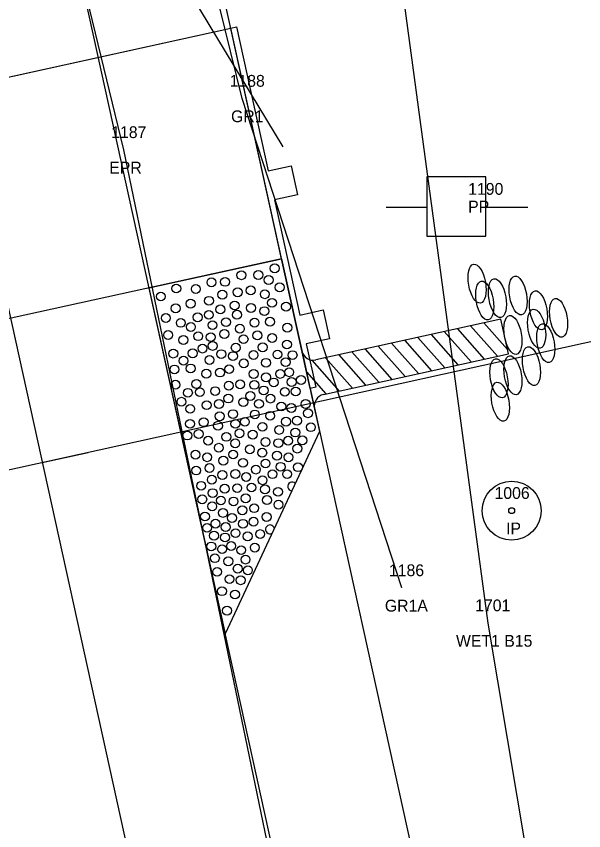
# Model space of a CAD drawing. Extents: x 2522090 to 2524658, y 882711 to 887512.
# Drawn here: x 2523808.5 to 2523856.5, y 884993.3 to 885062.2 of the extents above; entities that cross this region are included whole.
import ezdxf

# ---------------------------------------------------------------- set-up
doc = ezdxf.new("R2010")
doc.units = 0
for name, color, linetype in [('RD_EV_JurisArea', 7, 'Continuous'), ('RD_EX_DV_Prop_txCode', 7, 'Continuous'), ('RD_EX_DV_PropPin', 7, 'Continuous'), ('RD_EX_GuardRail', 7, 'Continuous'), ('RD_EX_GuardRail_txCode', 7, 'Continuous'), ('RD_EX_H2O_WetLd_txCode', 7, 'Continuous'), ('RD_EX_Road', 7, 'Continuous'), ('RD_EX_Road_txCode', 7, 'Continuous'), ('RD_EX_UT', 7, 'Continuous'), ('RD_EX_UT_txCode', 7, 'Continuous'), ('RD_HC_Cl', 7, 'Continuous'), ('RD_HC_Data_Tic', 7, 'Continuous'), ('RD_PD_Bridge', 7, 'Continuous'), ('RD_PD_Final_TrvlWay', 7, 'Continuous'), ('RD_PD_GR', 7, 'Continuous'), ('RD_PD_PatLn5', 7, 'Continuous'), ('RD_PD_PatLn6', 7, 'Continuous'), ('RD_PD_PaveShd', 7, 'Continuous'), ('RD_SMD_Locator', 7, 'Continuous')]:
    doc.layers.add(name, color=color, linetype=linetype)

# ---------------------------------------------------------------- blocks, each defined once
blk = doc.blocks.new('TBC1')
at = {"layer": 'RD_PD_GR'}
blk.add_lwpolyline([(12.5, 2.5), (15, 2.5), (15, 0.492), (25, 0.492), (25, 2.5), (27.5, 2.5), (27.5, 0.492), (31.25, 0.492), (31.25, 0), (0, 0), (0, 0.492), (12.5, 0.492)], close=True, dxfattribs=at)

msp = doc.modelspace()

# ---------------------------------------------------------------- linework, layer by layer
at = {"layer": 'RD_EV_JurisArea'}
msp.add_lwpolyline([(2523944.864, 884550.08), (2523910.413, 884709.577), (2523888.007, 884815.03), (2523863.93, 884918.366), (2523848.427, 885010.841), (2523837.066, 885095.132), (2523817.825, 885104.474)], dxfattribs=at)
at = {"layer": 'RD_EX_DV_PropPin'}
for centre, radius in [((2523850.412, 885020.357), 2.499), ((2523850.412, 885020.358), 0.25)]:
    msp.add_circle(centre, radius, dxfattribs=at)
at = {"layer": 'RD_EX_GuardRail'}
msp.add_lwpolyline([(2523841.112, 885013.814), (2523827.604, 885055.265), (2523819.275, 885089.086)], dxfattribs=at)
at = {"layer": 'RD_EX_Road'}
for p, q in [((2523817.578, 885050.917), (2523809.375, 885084.881)), ((2523837.97, 884952.456), (2523817.578, 885050.917))]:
    msp.add_line(p, q, dxfattribs=at)
at = {"layer": 'RD_EX_UT'}
for p, q in [((2523848.225, 885048.623), (2523843.225, 885048.623)), ((2523843.225, 885048.623), (2523843.225, 885043.623)), ((2523848.225, 885043.623), (2523848.225, 885048.623)), ((2523839.793, 885046.061), (2523843.263, 885046.061)), ((2523848.153, 885046.061), (2523851.793, 885046.061)), ((2523843.225, 885043.623), (2523848.225, 885043.623))]:
    msp.add_line(p, q, dxfattribs=at)
at = {"layer": 'RD_HC_Cl'}
msp.add_line((2523641.165, 885794.201), (2524197.759, 883266.557), dxfattribs=at)
at = {"layer": 'RD_HC_Data_Tic'}
msp.add_line((2523810.669, 885024.44), (2523814.575, 885025.3), dxfattribs=at)
at = {"layer": 'RD_PD_Bridge'}
for p, q in [((2523780.729, 885051.128), (2523826.629, 885061.235)), ((2523830.93, 885041.703), (2523785.03, 885031.596))]:
    msp.add_line(p, q, dxfattribs=at)
for points in [[(2523830.93, 885041.703), (2523794.372, 885207.726)], [(2523780.729, 885051.128), (2523826.629, 885061.235)]]:
    msp.add_lwpolyline(points, dxfattribs=at)
at = {"layer": 'RD_PD_Final_TrvlWay'}
msp.add_line((2523722.39, 885481.141), (2524037.438, 884050.417), dxfattribs=at)
at = {"layer": 'RD_PD_GR'}
msp.add_line((2523833.35, 885030.716), (2523900.015, 884727.969), dxfattribs=at)
at = {"layer": 'RD_PD_PatLn5'}
msp.add_line((2523888.797, 885041.644), (2523732.541, 885007.236), dxfattribs=at)
at = {"layer": 'RD_PD_PatLn6'}
msp.add_line((2523748.348, 885188.144), (2523831.037, 885051.167), dxfattribs=at)
at = {"layer": 'RD_PD_PaveShd'}
for p, q in [((2523819.699, 885039.23), (2523830.93, 885041.703)), ((2523832.866, 885032.914), (2523830.93, 885041.703)), ((2523830.93, 885041.703), (2523832.866, 885032.914)), ((2523819.699, 885039.23), (2523826.151, 885009.932)), ((2523849.487, 885036.583), (2523833.843, 885033.129)), ((2523850.134, 885033.653), (2523849.487, 885036.583)), ((2523850.134, 885033.653), (2523849.487, 885036.583)), ((2523845.826, 885035.775), (2523848.1, 885033.204)), ((2523845.826, 885035.775), (2523848.1, 885033.204)), ((2523846.943, 885036.021), (2523849.217, 885033.451)), ((2523846.943, 885036.021), (2523849.217, 885033.451)), ((2523848.06, 885036.268), (2523850.054, 885034.014)), ((2523848.06, 885036.268), (2523850.054, 885034.014)), ((2523842.475, 885035.035), (2523844.749, 885032.465)), ((2523842.475, 885035.035), (2523844.749, 885032.465)), ((2523843.592, 885035.282), (2523845.866, 885032.711)), ((2523843.592, 885035.282), (2523845.866, 885032.711)), ((2523844.709, 885035.528), (2523846.983, 885032.958)), ((2523844.709, 885035.528), (2523846.983, 885032.958)), ((2523839.124, 885034.295), (2523841.398, 885031.725)), ((2523839.124, 885034.295), (2523841.398, 885031.725)), ((2523840.241, 885034.542), (2523842.515, 885031.972)), ((2523840.241, 885034.542), (2523842.515, 885031.972)), ((2523841.358, 885034.788), (2523843.632, 885032.218)), ((2523841.358, 885034.788), (2523843.632, 885032.218)), ((2523834.487, 885030.199), (2523850.134, 885033.653)), ((2523835.773, 885033.556), (2523838.047, 885030.985)), ((2523835.773, 885033.556), (2523838.047, 885030.985)), ((2523836.89, 885033.802), (2523839.164, 885031.232)), ((2523836.89, 885033.802), (2523839.164, 885031.232)), ((2523838.007, 885034.049), (2523840.281, 885031.478)), ((2523838.007, 885034.049), (2523840.281, 885031.478)), ((2523832.866, 885032.914), (2523833.511, 885029.984)), ((2523833.492, 885033.115), (2523835.813, 885030.492)), ((2523834.656, 885033.309), (2523836.93, 885030.739)), ((2523834.656, 885033.309), (2523836.93, 885030.739)), ((2523833.042, 885032.115), (2523834.696, 885030.246)), ((2523833.08, 885031.943), (2523833.08, 885031.943)), ((2523833.511, 885029.984), (2523834.156, 885027.054)), ((2523834.156, 885027.054), (2523826.151, 885009.932))]:
    msp.add_line(p, q, dxfattribs=at)
for centre in [(2523830.349, 885040.885), (2523830.349, 885040.885), (2523827.534, 885040.3), (2523827.534, 885040.3), (2523828.967, 885040.325), (2523828.967, 885040.325), (2523828.967, 885040.325), (2523824.999, 885039.698), (2523824.999, 885039.698), (2523826.153, 885039.739), (2523826.153, 885039.739), (2523829.845, 885039.899), (2523822.02, 885039.178), (2523822.02, 885039.178), (2523823.673, 885039.133), (2523823.673, 885039.133), (2523827.222, 885038.86), (2523827.222, 885038.86), (2523828.326, 885039.017), (2523828.326, 885039.017), (2523829.513, 885038.692), (2523829.513, 885038.692), (2523830.772, 885039.275), (2523830.772, 885039.275), (2523820.715, 885038.501), (2523820.715, 885038.501), (2523824.791, 885038.139), (2523824.791, 885038.139), (2523825.918, 885038.659), (2523825.918, 885038.659), (2523821.973, 885037.498), (2523821.973, 885037.498), (2523823.233, 885037.898), (2523823.233, 885037.898), (2523825.757, 885037.407), (2523825.757, 885037.407), (2523826.962, 885037.739), (2523826.962, 885037.739), (2523828.347, 885037.529), (2523828.347, 885037.529), (2523830.13, 885037.967), (2523830.13, 885037.967), (2523831.317, 885037.642), (2523831.317, 885037.642), (2523821.137, 885036.679), (2523821.137, 885036.679), (2523823.836, 885036.738), (2523823.836, 885036.738), (2523824.78, 885036.947), (2523824.78, 885036.947), (2523827.161, 885036.956), (2523827.161, 885036.956), (2523829.482, 885037.263), (2523829.482, 885037.263), (2523822.403, 885036.265), (2523822.403, 885036.265), (2523823.257, 885035.918), (2523823.257, 885035.918), (2523825.086, 885036.073), (2523825.086, 885036.073), (2523826.234, 885036.326), (2523826.234, 885036.326), (2523828.647, 885036.286), (2523828.647, 885036.286), (2523829.96, 885036.364), (2523829.96, 885036.364), (2523821.33, 885035.236), (2523821.33, 885035.236), (2523826.089, 885035.32), (2523826.089, 885035.32), (2523827.408, 885035.773), (2523827.408, 885035.773), (2523831.42, 885035.863), (2523831.42, 885035.863), (2523822.624, 885034.82), (2523822.624, 885034.82), (2523823.878, 885035.137), (2523823.878, 885035.137), (2523824.938, 885035.058), (2523827.719, 885034.884), (2523827.719, 885034.884), (2523828.889, 885035.205), (2523828.889, 885035.205), (2523830.139, 885034.988), (2523830.139, 885034.988), (2523824.24, 885034.09), (2523824.24, 885034.09), (2523825.101, 885034.315), (2523825.101, 885034.315), (2523827.057, 885034.167), (2523827.057, 885034.167), (2523829.333, 885034.196), (2523829.333, 885034.196), (2523831.389, 885034.434), (2523831.389, 885034.434), (2523821.767, 885033.666), (2523821.767, 885033.666), (2523823.407, 885033.689), (2523823.407, 885033.689), (2523825.83, 885033.62), (2523825.83, 885033.62), (2523826.817, 885033.452), (2523826.817, 885033.452), (2523828.563, 885033.542), (2523828.563, 885033.542), (2523830.587, 885033.586), (2523830.587, 885033.586), (2523831.867, 885033.535), (2523831.867, 885033.535), (2523822.633, 885033.066), (2523822.633, 885033.066), (2523824.832, 885033.125), (2523824.832, 885033.125), (2523827.734, 885032.835), (2523827.734, 885032.835), (2523829.618, 885032.888), (2523829.618, 885032.888), (2523831.282, 885032.938), (2523821.864, 885032.324), (2523821.864, 885032.324), (2523823.244, 885032.408), (2523823.244, 885032.408), (2523824.564, 885031.963), (2523824.564, 885031.963), (2523825.721, 885032.06), (2523825.721, 885032.06), (2523826.497, 885032.349), (2523826.497, 885032.349), (2523828.577, 885031.941), (2523828.577, 885031.941), (2523830.823, 885031.944), (2523830.823, 885031.944), (2523831.582, 885032.085), (2523831.582, 885032.085), (2523823.725, 885031.088), (2523823.725, 885031.088), (2523829.621, 885031.656), (2523829.621, 885031.656), (2523830.274, 885031.22), (2523830.274, 885031.22), (2523831.784, 885031.259), (2523831.784, 885031.259), (2523832.587, 885031.427), (2523832.587, 885031.427), (2523821.953, 885031.028), (2523821.953, 885031.028), (2523824.02, 885030.397), (2523824.02, 885030.397), (2523825.316, 885030.486), (2523825.316, 885030.486), (2523826.467, 885030.948), (2523826.467, 885030.948), (2523827.428, 885031.058), (2523827.428, 885031.058), (2523828.627, 885031.016), (2523828.627, 885031.016), (2523829.418, 885030.543), (2523829.418, 885030.543), (2523831.214, 885030.426), (2523831.214, 885030.426), (2523832.127, 885030.452), (2523832.127, 885030.452), (2523823.006, 885030.346), (2523823.006, 885030.346), (2523826.429, 885029.856), (2523826.429, 885029.856), (2523828.295, 885030.079), (2523828.295, 885030.079), (2523830.001, 885029.855), (2523830.001, 885029.855), (2523822.459, 885029.586), (2523824.598, 885029.295), (2523824.598, 885029.295), (2523825.639, 885029.394), (2523825.639, 885029.394), (2523827.701, 885029.554), (2523827.701, 885029.554), (2523829.019, 885029.41), (2523829.019, 885029.41), (2523830.914, 885029.182), (2523830.914, 885029.182), (2523831.766, 885029.063), (2523831.766, 885029.063), (2523832.97, 885029.396), (2523832.97, 885029.396), (2523823.203, 885028.987), (2523823.203, 885028.987), (2523825.691, 885028.358), (2523825.691, 885028.358), (2523826.825, 885028.541), (2523826.825, 885028.541), (2523828.676, 885028.512), (2523828.676, 885028.512), (2523829.968, 885028.398), (2523829.968, 885028.398), (2523833.17, 885028.613), (2523833.17, 885028.613), (2523823.189, 885027.719), (2523823.189, 885027.719), (2523824.341, 885027.852), (2523824.341, 885027.852), (2523827.027, 885027.715), (2523827.027, 885027.715), (2523827.831, 885027.884), (2523827.831, 885027.884), (2523831.312, 885027.895), (2523831.312, 885027.895), (2523832.243, 885027.983), (2523832.243, 885027.983), (2523825.558, 885027.553), (2523825.558, 885027.553), (2523829.314, 885027.463), (2523829.314, 885027.463), (2523830.736, 885027.201), (2523830.736, 885027.201), (2523832.098, 885026.977), (2523832.098, 885026.977), (2523832.098, 885026.977), (2523833.417, 885027.43), (2523833.417, 885027.43), (2523822.96, 885026.723), (2523822.96, 885026.723), (2523823.922, 885026.86), (2523823.922, 885026.86), (2523824.722, 885026.285), (2523824.722, 885026.285), (2523826.258, 885026.612), (2523826.258, 885026.612), (2523827.371, 885026.909), (2523827.371, 885026.909), (2523828.495, 885026.805), (2523828.495, 885026.805), (2523831.494, 885026.285), (2523831.494, 885026.285), (2523832.697, 885026.313), (2523825.619, 885025.69), (2523825.619, 885025.69), (2523827.01, 885026.061), (2523827.01, 885026.061), (2523829.579, 885026.177), (2523829.579, 885026.177), (2523830.668, 885026.083), (2523830.668, 885026.083), (2523832.268, 885025.62), (2523832.268, 885025.62), (2523823.647, 885025.109), (2523823.647, 885025.109), (2523824.637, 885024.887), (2523824.637, 885024.887), (2523826.84, 885025.117), (2523826.84, 885025.117), (2523828.25, 885025.557), (2523828.25, 885025.557), (2523829.299, 885025.269), (2523829.299, 885025.269), (2523830.547, 885025.024), (2523830.547, 885025.024), (2523831.521, 885024.88), (2523831.521, 885024.88), (2523826.002, 885024.601), (2523826.002, 885024.601), (2523827.675, 885024.414), (2523827.675, 885024.414), (2523829.58, 885024.354), (2523829.58, 885024.354), (2523823.705, 885023.759), (2523823.705, 885023.759), (2523824.84, 885023.97), (2523824.84, 885023.97), (2523828.762, 885023.842), (2523828.762, 885023.842), (2523830.854, 885024.079), (2523830.854, 885024.079), (2523832.325, 885024.042), (2523825.026, 885022.984), (2523825.026, 885022.984), (2523825.92, 885023.378), (2523825.92, 885023.378), (2523827.027, 885023.472), (2523827.027, 885023.472), (2523827.938, 885023.219), (2523827.938, 885023.219), (2523829.325, 885022.938), (2523829.325, 885022.938), (2523830.17, 885023.448), (2523830.17, 885023.448), (2523831.406, 885023.456), (2523831.406, 885023.456), (2523824.131, 885022.47), (2523824.131, 885022.47), (2523826.119, 885022.219), (2523826.119, 885022.219), (2523827.181, 885022.266), (2523827.181, 885022.266), (2523828.389, 885022.322), (2523828.389, 885022.322), (2523829.53, 885022.168), (2523829.53, 885022.168), (2523825.102, 885021.848), (2523825.102, 885021.848), (2523830.64, 885021.96), (2523830.64, 885021.96), (2523824.22, 885021.325), (2523824.22, 885021.325), (2523825.799, 885021.225), (2523825.799, 885021.225), (2523826.869, 885021.144), (2523826.869, 885021.144), (2523827.898, 885021.404), (2523827.898, 885021.404), (2523829.699, 885021.26), (2523829.699, 885021.26), (2523830.672, 885020.872), (2523825.063, 885020.725), (2523825.063, 885020.725), (2523825.975, 885020.172), (2523825.975, 885020.172), (2523827.612, 885020.396), (2523827.612, 885020.396), (2523828.618, 885020.568), (2523828.618, 885020.568), (2523824.449, 885019.865), (2523824.449, 885019.865), (2523826.735, 885019.741), (2523826.735, 885019.741), (2523828.563, 885019.424), (2523828.563, 885019.424), (2523829.668, 885019.831), (2523829.668, 885019.831), (2523824.631, 885018.908), (2523824.631, 885018.908), (2523825.343, 885019.265), (2523825.343, 885019.265), (2523826.207, 885018.972), (2523826.207, 885018.972), (2523827.668, 885019.251), (2523827.668, 885019.251), (2523825.216, 885018.247), (2523825.216, 885018.247), (2523826.153, 885018.093), (2523826.153, 885018.093), (2523827.041, 885018.456), (2523827.041, 885018.456), (2523828.067, 885018.184), (2523828.067, 885018.184), (2523829.124, 885018.379), (2523829.124, 885018.379), (2523824.984, 885017.331), (2523824.984, 885017.331), (2523826.67, 885017.372), (2523826.67, 885017.372), (2523825.9, 885017.099), (2523825.9, 885017.099), (2523827.515, 885017.016), (2523827.515, 885017.016), (2523828.667, 885017.234), (2523828.667, 885017.234), (2523825.292, 885016.334), (2523825.292, 885016.334), (2523826.43, 885016.072), (2523826.43, 885016.072), (2523827.885, 885016.22), (2523827.226, 885015.446), (2523827.226, 885015.446), (2523828.085, 885015.311), (2523825.478, 885015.184), (2523825.478, 885015.184), (2523826.53, 885014.559), (2523826.53, 885014.559), (2523827.471, 885014.469), (2523827.471, 885014.469), (2523825.89, 885013.54), (2523825.89, 885013.54), (2523826.996, 885013.264), (2523826.996, 885013.264), (2523826.319, 885011.894), (2523826.319, 885011.894)]:
    msp.add_circle(centre, 0.375, dxfattribs=at)
for centre, radius, start, end in [((2523833.627, 885034.106), 1, 192.41848, 282.4481), ((2523834.703, 885029.223), 1, 102.4481, 192.41848), ((2523831.832, 885022.414), 0.375, 42.98701, 266.8976), ((2523829.956, 885018.778), 0.375, 11.79981, 298.0848)]:
    msp.add_arc(centre, radius, start, end, dxfattribs=at)
for centre in [(2523847.484, 885039.588), (2523847.484, 885039.588), (2523848.138, 885038.158), (2523848.138, 885038.158), (2523849.206, 885038.36), (2523849.206, 885038.36), (2523850.961, 885038.589), (2523850.961, 885038.589), (2523852.682, 885037.334), (2523852.682, 885037.334), (2523854.384, 885036.696), (2523854.384, 885036.696), (2523852.53, 885035.772), (2523852.53, 885035.772), (2523850.517, 885035.244), (2523850.517, 885035.244), (2523853.297, 885034.546), (2523853.297, 885034.546), (2523852.083, 885032.6), (2523852.083, 885032.6), (2523850.519, 885031.826), (2523850.519, 885031.826), (2523849.34, 885031.575), (2523849.456, 885029.59)]:
    msp.add_ellipse(centre, major_axis=(0.292, -1.645), ratio=0.429445, dxfattribs=at)
at = {"layer": 'RD_SMD_Locator'}
for centre in [(2523827.604, 885055.265), (2523817.578, 885050.917), (2523841.112, 885013.814), (2523848.427, 885010.841)]:
    msp.add_circle(centre, 0.001, dxfattribs=at)

# ---------------------------------------------------------------- block references
at = {"layer": 'RD_PD_Bridge', "rotation": -77.58151740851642}
msp.add_blockref('TBC1', (2523826.629, 885061.235), dxfattribs=at)

# ---------------------------------------------------------------- texts
at = {"layer": 'RD_EX_DV_Prop_txCode'}
for s, p in [('1006', (2523848.964, 885021.358)), ('IP', (2523849.94, 885018.358))]:
    msp.add_text(s, height=1, dxfattribs=at).set_placement(p)
at = {"layer": 'RD_EX_GuardRail_txCode'}
for s, p in [('1188', (2523826.541, 885056.265)), ('GR1', (2523826.659, 885053.265)), ('1186', (2523840.026, 885014.814)), ('GR1A', (2523839.679, 885011.814))]:
    msp.add_text(s, height=1, dxfattribs=at).set_placement(p)
at = {"layer": 'RD_EX_H2O_WetLd_txCode'}
for s, p in [('1701', (2523847.325, 885011.841)), ('WET1 B15', (2523845.703, 885008.841))]:
    msp.add_text(s, height=1, dxfattribs=at).set_placement(p)
at = {"layer": 'RD_EX_Road_txCode'}
for s, p in [('1187', (2523816.515, 885051.917)), ('EPR', (2523816.35, 885048.917))]:
    msp.add_text(s, height=1, dxfattribs=at).set_placement(p)
at = {"layer": 'RD_EX_UT_txCode'}
for s, p in [('1190', (2523846.734, 885047.114)), ('PP', (2523846.734, 885045.614))]:
    msp.add_text(s, height=1, dxfattribs=at).set_placement(p)

doc.saveas('drawing.dxf')
